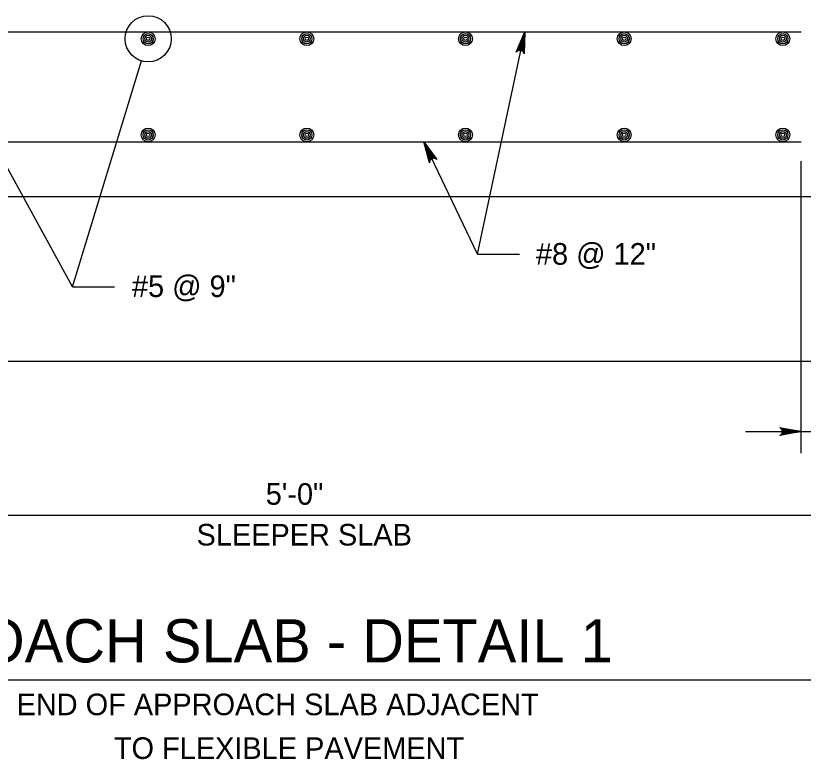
# Model space of a CAD drawing. Extents: x 638079 to 640019, y 297691 to 298879.
# Drawn here: x 639301.6 to 639410.8, y 298652.4 to 298755.6 of the extents above; entities that cross this region are included whole.
import ezdxf

# ---------------------------------------------------------------- set-up
doc = ezdxf.new("R2010")
doc.units = 0
doc.layers.add('1', color=7, linetype='Continuous')

msp = doc.modelspace()

# ---------------------------------------------------------------- linework, layer by layer
at = {"layer": '1'}
for p, q in [((639273.36, 298753.32), (639410.52, 298753.32)), ((639365.63, 298722.48), (639372.17, 298753.32)), ((639319.93, 298752.37), (639319.93, 298752.37)), ((639309.44, 298717.94), (639318.99, 298749.3)), ((639273.36, 298738.08), (639410.52, 298738.08)), ((639365.63, 298722.48), (639358.18, 298738.08)), ((639309.44, 298717.94), (639299.45, 298736.22)), ((639410.52, 298694.87), (639410.52, 298735.38)), ((639265.74, 298730.46), (639418.14, 298730.46)), ((639365.63, 298722.48), (639371.43, 298722.48)), ((639309.44, 298717.94), (639315.26, 298717.94)), ((639250.5, 298707.6), (639433.38, 298707.6)), ((639402.82, 298697.84), (639448.88, 298697.84)), ((639224.58, 298686.26), (639418.14, 298686.26)), ((639272.75, 298663.4), (639416.31, 298663.4))]:
    msp.add_line(p, q, dxfattribs=at)
for points in [[(639372.17, 298753.32), (639372.1, 298750.28), (639372.04, 298750.41), (639371.99, 298750.54), (639371.9, 298750.62), (639371.82, 298750.7), (639371.72, 298750.74), (639371.63, 298750.77), (639371.53, 298750.78), (639371.43, 298750.78), (639371.32, 298750.74), (639371.21, 298750.71), (639371.11, 298750.61), (639371, 298750.51), (639372.17, 298753.32), (639371.11, 298750.61), (639371.21, 298750.71), (639372.17, 298753.32), (639371.32, 298750.74), (639371.43, 298750.78), (639372.17, 298753.32), (639371.53, 298750.78), (639371.63, 298750.77), (639372.17, 298753.32), (639371.72, 298750.74), (639371.82, 298750.7), (639372.17, 298753.32), (639371.9, 298750.62), (639371.99, 298750.54), (639372.17, 298753.32), (639372.04, 298750.41)], [(639358.18, 298738.08), (639359.97, 298735.63), (639359.85, 298735.7), (639359.73, 298735.76), (639359.61, 298735.78), (639359.5, 298735.79), (639359.4, 298735.76), (639359.3, 298735.73), (639359.22, 298735.67), (639359.14, 298735.61), (639359.07, 298735.52), (639359.01, 298735.42), (639358.98, 298735.28), (639358.96, 298735.14), (639358.18, 298738.08), (639358.98, 298735.28), (639359.01, 298735.42), (639358.18, 298738.08), (639359.07, 298735.52), (639359.14, 298735.61), (639358.18, 298738.08), (639359.22, 298735.67), (639359.3, 298735.73), (639358.18, 298738.08), (639359.4, 298735.76), (639359.5, 298735.79), (639358.18, 298738.08), (639359.61, 298735.78), (639359.73, 298735.76), (639358.18, 298738.08), (639359.85, 298735.7)], [(639410.52, 298697.84), (639407.54, 298697.28), (639407.65, 298697.36), (639407.77, 298697.44), (639407.83, 298697.54), (639407.89, 298697.64), (639407.9, 298697.74), (639407.92, 298697.84), (639407.9, 298697.94), (639407.89, 298698.04), (639407.83, 298698.14), (639407.77, 298698.24), (639407.65, 298698.32), (639407.54, 298698.4), (639410.52, 298697.84), (639407.65, 298698.32), (639407.77, 298698.24), (639410.52, 298697.84), (639407.83, 298698.14), (639407.89, 298698.04), (639410.52, 298697.84), (639407.9, 298697.94), (639407.92, 298697.84), (639410.52, 298697.84), (639407.9, 298697.74), (639407.89, 298697.64), (639410.52, 298697.84), (639407.83, 298697.54), (639407.77, 298697.44), (639410.52, 298697.84), (639407.65, 298697.36)]]:
    msp.add_lwpolyline(points, dxfattribs=at)
for centre, radius in [((639319.93, 298752.37), 3.2), ((639319.93, 298752.37), 0.952), ((639319.93, 298752.37), 0.714), ((639341.94, 298752.37), 0.952), ((639341.94, 298752.37), 0.714), ((639363.95, 298752.37), 0.952), ((639363.95, 298752.37), 0.714), ((639385.97, 298752.37), 0.952), ((639385.97, 298752.37), 0.714), ((639407.98, 298752.37), 0.952), ((639407.98, 298752.37), 0.714), ((639319.93, 298752.37), 0.476), ((639319.93, 298752.37), 0.238), ((639341.94, 298752.37), 0.476), ((639341.94, 298752.37), 0.238), ((639363.95, 298752.37), 0.476), ((639363.95, 298752.37), 0.238), ((639385.97, 298752.37), 0.476), ((639385.97, 298752.37), 0.238), ((639407.98, 298752.37), 0.476), ((639407.98, 298752.37), 0.238), ((639319.93, 298739.03), 0.952), ((639341.94, 298739.03), 0.952), ((639363.95, 298739.03), 0.952), ((639385.97, 298739.03), 0.952), ((639407.98, 298739.03), 0.952), ((639319.93, 298739.03), 0.714), ((639319.93, 298739.03), 0.476), ((639319.93, 298739.03), 0.238), ((639341.94, 298739.03), 0.714), ((639341.94, 298739.03), 0.476), ((639341.94, 298739.03), 0.238), ((639363.95, 298739.03), 0.714), ((639363.95, 298739.03), 0.476), ((639363.95, 298739.03), 0.238), ((639385.97, 298739.03), 0.714), ((639385.97, 298739.03), 0.476), ((639385.97, 298739.03), 0.238), ((639407.98, 298739.03), 0.714), ((639407.98, 298739.03), 0.476), ((639407.98, 298739.03), 0.238)]:
    msp.add_circle(centre, radius, dxfattribs=at)

# ---------------------------------------------------------------- texts
for s, height, p in [('#8 @ 12"', 3, (639373.73, 298721.01)), ('#5 @ 9"', 3, (639317.68, 298716.52)), ('5\'-0"', 3, (639336.24, 298687.69)), ('SLEEPER SLAB', 3, (639326.64, 298682.03)), ('APPROACH SLAB - DETAIL 1', 6, (639274.71, 298665.81)), ('END OF APPROACH SLAB ADJACENT', 3, (639301.67, 298658.48)), ('TO FLEXIBLE PAVEMENT', 3, (639315.17, 298652.41))]:
    msp.add_text(s, height=height, dxfattribs=at).set_placement(p)

doc.saveas('drawing.dxf')
